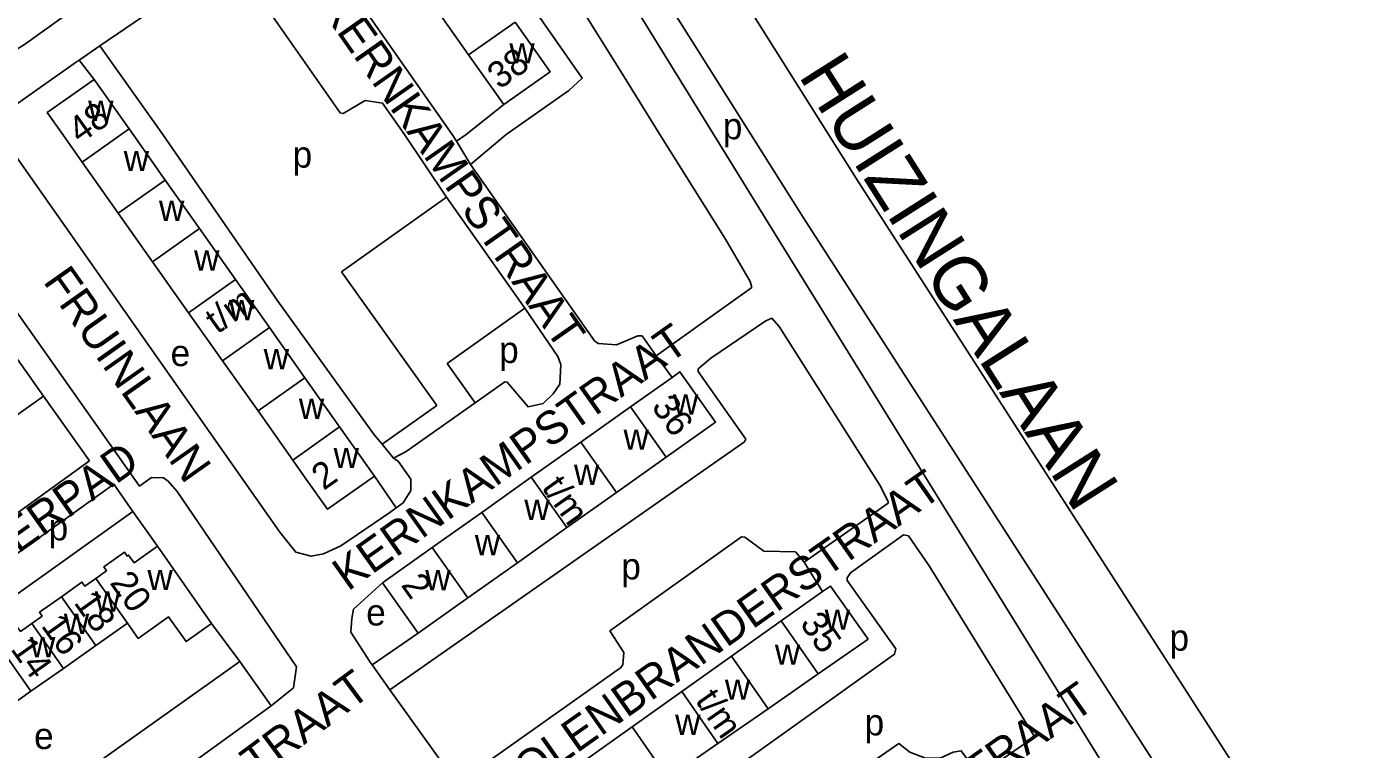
# Model space of a CAD drawing. Extents: x 158848 to 160613, y 385889 to 387762.
# Drawn here: x 160079.5 to 160280.6, y 387006.5 to 387116.4 of the extents above; entities that cross this region are included whole.
import ezdxf

# ---------------------------------------------------------------- set-up
doc = ezdxf.new("R2010")
doc.units = 0
for name, color, linetype in [('BLT_Basislijn', 7, 'Continuous'), ('BLT_Bebouwing', 7, 'Continuous'), ('BLT_Centroide', 7, 'Continuous'), ('BLT_Huisnummer', 7, 'Continuous'), ('BLT_Huisnummer_ tussenligend', 7, 'Continuous'), ('BLT_Huisnummer_reeks', 7, 'Continuous'), ('BLT_Onderverdeling_panden', 7, 'Continuous'), ('BLT_Straatnaam', 7, 'Continuous'), ('BLT_Straatnaam_hoofdweg', 7, 'Continuous')]:
    doc.layers.add(name, color=color, linetype=linetype)

msp = doc.modelspace()

# ---------------------------------------------------------------- linework, layer by layer
at = {"layer": 'BLT_Basislijn'}
for p, q in [((160120.27, 387228.85), (160206.02, 387092.88)), ((160087.53, 387111.32), (160090.69, 387113.49)), ((160089.8, 387108.37), (160087.53, 387111.32)), ((160147.04, 387095.45), (160144.89, 387098.98)), ((160206.02, 387092.88), (160319.76, 386916.3)), ((160143.41, 387090.5), (160127.44, 387079.13)), ((160155.29, 387073.59), (160143.41, 387090.5)), ((160197.58, 387087.5), (160293.61, 386938.43)), ((160193.36, 387084.84), (160268.41, 386963.66)), ((160127.44, 387079.13), (160141.9, 387058.83)), ((160075.46, 387076.59), (160096.68, 387046.57)), ((160155.29, 387073.59), (160143.5, 387065.19)), ((160175.27, 387066.35), (160177.71, 387063.09)), ((160143.5, 387065.19), (160147.75, 387059.22)), ((160082.11, 387060.25), (160089.09, 387050.38)), ((160129.65, 387058.14), (160132.45, 387054.31)), ((160141.9, 387058.83), (160133.6, 387052.93)), ((160133.6, 387052.93), (160132.45, 387054.31)), ((160133.6, 387052.93), (160135.34, 387050.83)), ((160089.09, 387050.38), (160030.55, 387008.25)), ((160135.76, 387043.25), (160132.43, 387048.08)), ((160092.78, 387046.87), (160033.56, 387004.36)), ((160095.68, 387042.71), (160092.78, 387046.87)), ((160197.8, 387034.98), (160200.59, 387030.52)), ((160111.96, 387019.88), (160107.64, 387025.65)), ((160132.1, 387019.41), (160139.11, 387024.21)), ((160053.61, 386978.5), (160111.96, 387019.88)), ((160111.96, 387019.88), (160116.71, 387013.17)), ((160132.1, 387019.41), (160134.78, 387015.61)), ((160134.78, 387015.61), (160145.04, 387001.33))]:
    msp.add_line(p, q, dxfattribs=at)
for points in [[(160108.41, 387222.5), (160121.56, 387208.06), (160197.58, 387087.5)], [(160108.41, 387222.5), (160193.36, 387084.84)], [(160175.27, 387066.35), (160189.82, 387076.75), (160189.6, 387077.67), (160185.82, 387084.09), (160175.86, 387100), (160170.14, 387109.18), (160127.57, 387177.26), (160126.03, 387176.83), (160111.03, 387166.28), (160110.95, 387165.8), (160119.18, 387154.29), (160119.6, 387154.29), (160127.52, 387159.75), (160128.51, 387159.51), (160164.03, 387108.56), (160162.02, 387106.67), (160152.45, 387100), (160147.04, 387095.45)], [(160112.9, 387144.8), (160108.43, 387141.31), (160109.47, 387136.09), (160109.21, 387135.2), (160079.21, 387113.67), (160072.92, 387109.76), (160069.56, 387109.86), (160067.54, 387111.42), (160063.46, 387117.49)], [(160144.89, 387098.98), (160144.27, 387100), (160112.9, 387144.8)], [(160143.41, 387090.5), (160136.99, 387100), (160133.68, 387104.78), (160131.03, 387105.16), (160127.68, 387103.18), (160127.21, 387103.28), (160116.57, 387118.51), (160116.47, 387118.99), (160119.5, 387121.95), (160119.35, 387124.53), (160116.47, 387128), (160113.45, 387128.27), (160110.42, 387126.95), (160090.69, 387113.49)], [(160129.65, 387058.14), (160117.72, 387074.65), (160100.23, 387100), (160090.69, 387113.49)], [(160087.53, 387111.32), (160086.79, 387110.81), (160077.3, 387104.11), (160076.35, 387102.52), (160076.31, 387100), (160076.37, 387098.89), (160118.05, 387039.54), (160120.49, 387036.53), (160122.8, 387035.89), (160124.7, 387036.28), (160127.31, 387037.47), (160134.78, 387042.54), (160135.76, 387043.25)], [(160152.09, 387104.54), (160146.38, 387100), (160144.89, 387098.98)], [(160175.27, 387066.35), (160173.13, 387069.4), (160172.48, 387069.4), (160169.23, 387068.01), (160166.47, 387068.25), (160165.89, 387068.65), (160147.04, 387095.45)], [(160134.78, 387015.61), (160188.74, 387053.3), (160188.9, 387053.71), (160181.68, 387063.98), (160181.68, 387064.36), (160183.62, 387066.02), (160191.97, 387071.7), (160192.89, 387072.07), (160193.99, 387070.8), (160209.32, 387046.71), (160210.56, 387044.2), (160210.56, 387043.94), (160197.8, 387034.98)], [(160155.29, 387073.59), (160160.33, 387066.26), (160160.77, 387065.04), (160160.64, 387062.05), (160159.63, 387060.6), (160158.08, 387059.14), (160155.81, 387058.6), (160152.64, 387062.38), (160152.28, 387062.41), (160147.75, 387059.22)], [(160147.75, 387059.22), (160137.26, 387051.82), (160135.34, 387050.83)], [(160135.34, 387050.83), (160136.06, 387050.36), (160137.96, 387047.63), (160137.96, 387045.91), (160136.78, 387044.01), (160135.76, 387043.25)], [(160096.68, 387046.57), (160098.51, 387047.86), (160100.33, 387047.81), (160101.08, 387047.3), (160102.42, 387045.74), (160120.56, 387019.09), (160120.14, 387015.91), (160116.71, 387013.17)], [(160036.52, 387000.48), (160095.68, 387042.71)], [(160095.68, 387042.71), (160099.42, 387037.41)], [(160197.8, 387034.98), (160196.47, 387036.58), (160191.66, 387036.69), (160188.77, 387038.81), (160188.26, 387038.85), (160168.25, 387024.55), (160170.38, 387021.28), (160170.21, 387019.41), (160169.88, 387018.95), (160145.04, 387001.33)], [(160158.04, 386982.81), (160211.55, 387021), (160211.71, 387021.8), (160204.34, 387032.22), (160204.34, 387032.61), (160204.86, 387033.39), (160212.92, 387039.14), (160213.67, 387038.98), (160216.8, 387034.43), (160232.71, 387008.66), (160232.39, 387008.12), (160224.35, 387002.62)], [(160133.68, 387031.86), (160129.27, 387027.83), (160128.98, 387026.44), (160128.83, 387024.34), (160131.81, 387019.82), (160132.1, 387019.41)], [(160053.61, 386978.5), (160058.61, 386972.96), (160060.74, 386973.02), (160074.51, 386982.64), (160116.71, 387013.17)], [(160190.57, 386992.51), (160212.19, 387007.43), (160213.84, 387006.12), (160216.26, 387005.18), (160218.55, 387005.28), (160220.45, 387006.12), (160221.67, 387006.3), (160224.35, 387002.62)]]:
    msp.add_lwpolyline(points, dxfattribs=at)
at = {"layer": 'BLT_Bebouwing'}
for p, q in [((160141.42, 387119.64), (160146.75, 387112.09)), ((160146.75, 387112.09), (160152.09, 387104.54)), ((160095.13, 387100.84), (160089.8, 387108.37)), ((160087.99, 387095.79), (160093.48, 387088.04)), ((160105.82, 387085.72), (160100.61, 387093.08)), ((160093.48, 387088.04), (160098.69, 387080.67)), ((160111.3, 387077.96), (160105.82, 387085.72)), ((160098.69, 387080.67), (160104.17, 387072.92)), ((160116.47, 387070.66), (160111.3, 387077.96)), ((160104.17, 387072.92), (160109.34, 387065.62)), ((160121.86, 387063.03), (160116.47, 387070.66)), ((160109.34, 387065.62), (160114.73, 387057.99)), ((160127.14, 387055.56), (160121.86, 387063.03)), ((160177.71, 387063.09), (160171.36, 387058.59)), ((160114.73, 387057.99), (160120.02, 387050.52)), ((160171.36, 387058.59), (160163.83, 387053.24)), ((160132.43, 387048.08), (160127.14, 387055.56)), ((160163.83, 387053.24), (160156.29, 387047.9)), ((160169.25, 387045.59), (160176.79, 387050.94)), ((160156.29, 387047.9), (160148.75, 387042.55)), ((160161.71, 387040.25), (160169.25, 387045.59)), ((160148.75, 387042.55), (160141.22, 387037.21)), ((160154.18, 387034.9), (160161.71, 387040.25)), ((160141.22, 387037.21), (160133.68, 387031.86)), ((160146.65, 387029.56), (160154.18, 387034.9)), ((160133.68, 387031.86), (160139.11, 387024.21)), ((160139.11, 387024.21), (160146.65, 387029.56)), ((160200.59, 387030.52), (160194.3, 387026.06)), ((160090.06, 387022.33), (160094.86, 387025.71)), ((160194.3, 387026.06), (160186.75, 387020.7)), ((160085.13, 387018.85), (160090.06, 387022.33)), ((160199.9, 387018.01), (160207.51, 387023.29)), ((160186.75, 387020.7), (160179.19, 387015.34)), ((160080.2, 387015.38), (160085.13, 387018.85)), ((160192.29, 387012.72), (160199.9, 387018.01)), ((160075.27, 387011.9), (160080.2, 387015.38)), ((160179.19, 387015.34), (160171.63, 387009.98)), ((160184.68, 387007.43), (160192.29, 387012.72)), ((160171.63, 387009.98), (160164.07, 387004.62)), ((160177.08, 387002.14), (160184.68, 387007.43))]:
    msp.add_line(p, q, dxfattribs=at)
for points in [[(160152.09, 387104.54), (160159.16, 387109.53), (160153.83, 387117.09)], [(160087.99, 387095.79), (160085.02, 387100), (160082.67, 387103.33), (160089.8, 387108.37)], [(160100.61, 387093.08), (160095.72, 387100), (160095.13, 387100.84)], [(160082.11, 387060.25), (160075.94, 387068.97)], [(160176.79, 387050.94), (160184.32, 387056.28), (160178.89, 387063.93), (160177.71, 387063.09)], [(160073.23, 387053.97), (160082.11, 387060.25)], [(160120.02, 387050.52), (160121.91, 387047.84), (160125.31, 387043.04), (160132.43, 387048.08)], [(160099.42, 387037.41), (160095.88, 387034.91), (160095.05, 387036.08), (160094.84, 387035.93), (160094.44, 387036.5), (160091.29, 387034.28), (160091.7, 387033.7), (160090.04, 387032.52)], [(160107.64, 387025.65), (160099.42, 387037.41)], [(160090.04, 387032.52), (160088.38, 387031.35), (160087.95, 387031.96), (160084.83, 387029.75)], [(160084.83, 387029.75), (160081.48, 387027.38), (160081.89, 387026.79), (160080.32, 387025.68)], [(160207.51, 387023.29), (160201.79, 387031.37), (160200.59, 387030.52)], [(160080.32, 387025.68), (160078.6, 387024.47), (160078.17, 387025.07), (160074.96, 387022.81)], [(160094.86, 387025.71), (160096.49, 387023.4), (160101.1, 387026.69), (160103.79, 387022.93), (160107.64, 387025.65)]]:
    msp.add_lwpolyline(points, dxfattribs=at)
at = {"layer": 'BLT_Onderverdeling_panden'}
for p, q in [((160146.75, 387112.09), (160153.83, 387117.09)), ((160087.99, 387095.79), (160095.13, 387100.84)), ((160093.48, 387088.04), (160100.61, 387093.08)), ((160098.69, 387080.67), (160105.82, 387085.72)), ((160104.17, 387072.92), (160111.3, 387077.96)), ((160109.34, 387065.62), (160116.47, 387070.66)), ((160114.73, 387057.99), (160121.86, 387063.03)), ((160176.79, 387050.94), (160171.36, 387058.59)), ((160120.02, 387050.52), (160127.14, 387055.56)), ((160169.25, 387045.59), (160163.83, 387053.24)), ((160161.71, 387040.25), (160156.29, 387047.9)), ((160154.18, 387034.9), (160148.75, 387042.55)), ((160146.65, 387029.56), (160141.22, 387037.21)), ((160094.86, 387025.71), (160090.04, 387032.52)), ((160090.06, 387022.33), (160084.83, 387029.75)), ((160085.13, 387018.85), (160080.32, 387025.68)), ((160199.9, 387018.01), (160194.3, 387026.06)), ((160080.2, 387015.38), (160074.96, 387022.81)), ((160192.29, 387012.72), (160186.75, 387020.7)), ((160184.68, 387007.43), (160179.19, 387015.34)), ((160177.08, 387002.14), (160171.63, 387009.98))]:
    msp.add_line(p, q, dxfattribs=at)

# ---------------------------------------------------------------- texts
at = {"layer": 'BLT_Centroide'}
for s, p in [('w', (160152.95, 387110.81)), ('w', (160088.89, 387102.08)), ('p', (160185.42, 387099.28)), ('p', (160119.99, 387094.97)), ('w', (160094.3, 387094.44)), ('w', (160099.66, 387086.88)), ('w', (160105, 387079.31)), ('w', (160110.31, 387071.78)), ('e', (160101.43, 387064.8)), ('p', (160151.4, 387065.27)), ('w', (160115.59, 387064.31)), ('w', (160120.94, 387056.77)), ('w', (160177.84, 387057.44)), ('w', (160170.31, 387052.09)), ('w', (160126.22, 387049.3)), ('w', (160162.77, 387046.75)), ('w', (160155.23, 387041.41)), ('p', (160082.89, 387038.31)), ('w', (160147.7, 387036.06)), ('p', (160169.98, 387032.38)), ('w', (160097.91, 387030.75)), ('w', (160140.16, 387030.72)), ('w', (160089.91, 387027.48)), ('e', (160131.18, 387025.37)), ('w', (160200.91, 387024.73)), ('w', (160085.19, 387024.08)), ('w', (160080.05, 387020.55)), ('p', (160253.35, 387021.54)), ('w', (160193.33, 387019.41)), ('w', (160185.73, 387014.08)), ('w', (160178.16, 387008.75)), ('p', (160206.98, 387008.67)), ('e', (160080.67, 387006.59))]:
    msp.add_text(s, height=4, dxfattribs=at).set_placement(p)
at = {"layer": 'BLT_Huisnummer'}
for s, p in [('20', (160092.08, 387031.85)), ('14', (160076.99, 387021.8))]:
    msp.add_text(s, height=4, rotation=305.4225, dxfattribs=at).set_placement(p)
at = {"layer": 'BLT_Huisnummer_ tussenligend'}
for s, p in [('18', (160086.61, 387028.84)), ('16', (160081.64, 387025.32))]:
    msp.add_text(s, height=4, rotation=305.4225, dxfattribs=at).set_placement(p)
at = {"layer": 'BLT_Huisnummer_reeks'}
for s, rotation, p in [('38', 35.2446, (160151.44, 387106.76)), ('48', 35.2639, (160087.67, 387098.49)), ('t/m', 35.2646, (160108.54, 387069.58)), ('36', 305.3459, (160174.46, 387058.63)), ('2', 35.269, (160124.71, 387045.81)), ('t/m', 305.3474, (160157.76, 387046.33)), ('2', 305.3453, (160136.38, 387031.51)), ('35', 304.7969, (160197.04, 387025.68)), ('t/m', 304.7992, (160181.12, 387013.96))]:
    msp.add_text(s, height=4, rotation=rotation, dxfattribs=at).set_placement(p)
at = {"layer": 'BLT_Straatnaam'}
for s, rotation, p in [('KERNKAMPSTRAAT', 304.9929, (160124, 387119.32)), ('FRUINLAAN', 305.2086, (160081.94, 387077.65)), ('KERNKAMPSTRAAT', 35.3416, (160128.4, 387030.49)), ('DE BOSCH KEMPERPAD', 35.3034, (160032.77, 387004.02)), ('COLENBRANDERSTRAAT', 35.1644, (160151.96, 386997.97)), ('VAN METERENSTRAAT', 36.625, (160072.21, 386970.38)), ('VAN PAPEBROECKSTRAAT', 35.2084, (160170.29, 386962.22))]:
    msp.add_text(s, height=5, rotation=rotation, dxfattribs=at).set_placement(p)
at = {"layer": 'BLT_Straatnaam_hoofdweg'}
msp.add_text('HUIZINGALAAN', height=8, rotation=302.4097, dxfattribs=at).set_placement((160196.8, 387108.98))

doc.saveas('drawing.dxf')
